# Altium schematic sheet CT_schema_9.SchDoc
size 278 x 170 mm
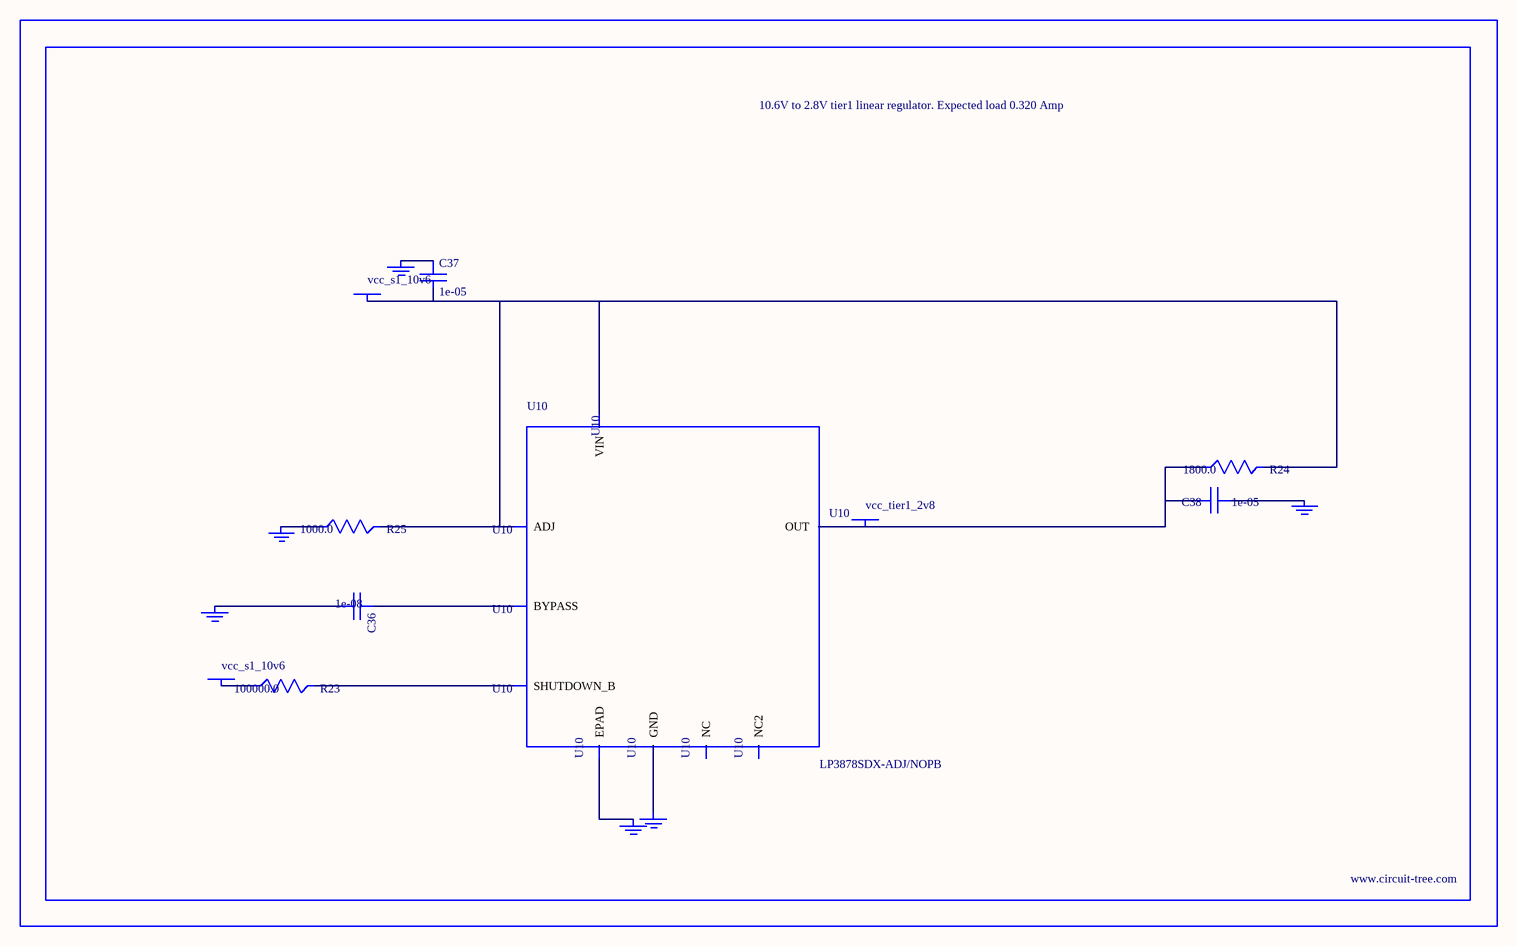
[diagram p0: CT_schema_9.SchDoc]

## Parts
BORDER8  (no value)
C36  1e-08  [C0402]
C37  1e-05  [C1206]
C38  1e-05  [C1210]
GND_INSTANCE_8_0  (no value)
GND_INSTANCE_8_1  (no value)
GND_INSTANCE_8_2  (no value)
GND_INSTANCE_8_3  (no value)
GND_INSTANCE_8_4  (no value)
GND_INSTANCE_8_5  (no value)
POWER_INSTANCE_8_0  vcc_s1_10v6
POWER_INSTANCE_8_1  vcc_s1_10v6
POWER_INSTANCE_8_2  vcc_tier1_2v8
R23  100000.0  [R0603]
R24  1800.0  [R0603]
R25  1000.0  [R0603]
U10  LP3878SDX-ADJ/NOPB  [WSON-8]

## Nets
NetC36_1: C36.1 U10.1(BYPASS)
NetC36_2: C36.2 GND_INSTANCE_8_0.0(GND)
NetC37_1: C37.1 GND_INSTANCE_8_1.0(GND)
NetC37_2: C37.2 POWER_INSTANCE_8_0.0(PWR) R24.2 R25.2 U10.4(VIN) U10.6(ADJ)
NetC38_1: C38.1 GND_INSTANCE_8_2.0(GND)
NetC38_2: C38.2 POWER_INSTANCE_8_2.0(PWR) R24.1 U10.5(OUT)
NetGND_INSTANCE_8_3_0: GND_INSTANCE_8_3.0(GND) R25.1
NetGND_INSTANCE_8_4_0: GND_INSTANCE_8_4.0(GND) U10.PAD(EPAD)
NetGND_INSTANCE_8_5_0: GND_INSTANCE_8_5.0(GND) U10.3(GND)
NetPOWER_INSTANCE_8_1_0: POWER_INSTANCE_8_1.0(PWR) R23.1
NetR23_2: R23.2 U10.8(SHUTDOWN_B)

Not connected (* = marked no-connect by the designer): U10 2(NC) 7(NC2)

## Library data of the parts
BORDER8 = BORDER_PAGE8
C36 = C0402C103K3RAC
C37 = C1206C106K3RACTU
C38 = GRM32DR61E106MA12L
GND_INSTANCE_8_0-GND_INSTANCE_8_5 = GND
POWER_INSTANCE_8_0-POWER_INSTANCE_8_2 = PWR
R23 = RC0603JR-07100KL
R24 = RC0603JR-071K8L
R25 = RC0603JR-071KL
